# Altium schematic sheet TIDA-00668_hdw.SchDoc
size 431 x 279 mm; Date: Not shown in title block; ApprovedBy: Not shown in title block; CheckedBy: Not shown in title block; Author: Not shown in title block; CompanyName: Not shown in title block; Engineer: Not shown in title block; Organization: Not shown in title block; Address1: Not shown in title block; Address2: Not shown in title block; Address3: Not shown in title block; Address4: Not shown in title block; DocumentNumber: 1; Revision: Use project parameter SCH_Rev; SheetNumber: 3; SheetTotal: 3; PageSetup: Record=PageOptions¦CenterHorizontal=True¦CenterVertical=True¦PrintScale=1.00¦XCorrection=1.00¦YCorrection=1.00¦PrintKind=0¦BorderSize=5000000¦LeftOffset=0¦BottomOffset=0¦Orientation=2¦PaperLength=1000¦PaperWidth=1000¦Scale=100¦PaperSource=15¦PrintQuality=600¦MediaType=1¦DitherType=10¦PaperKind=Letter¦PrintScaleMode=1
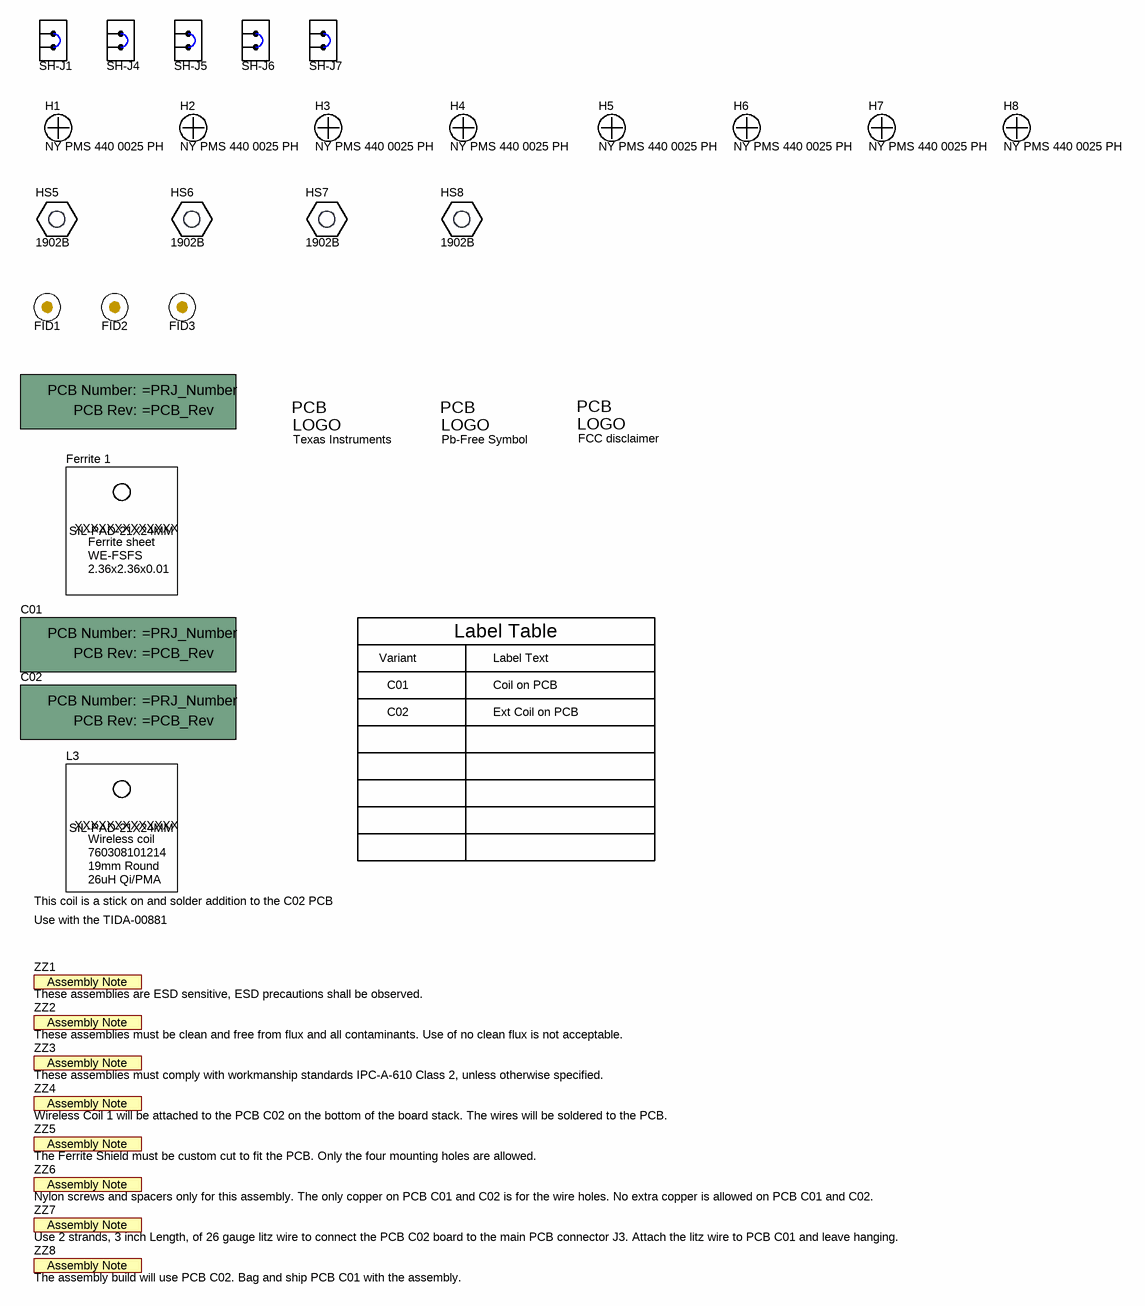
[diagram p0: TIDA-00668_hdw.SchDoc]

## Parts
(Parts that share a designator on the sheet are numbered #1, #2 ... from top to bottom, then left to right.)
!PCB1  Printed Circuit Board  (value not drawn)  (mechanical)
!PCB?#1  value C01  (hidden comment: Printed Circuit Board)  (mechanical)
!PCB?#2  value C02  (hidden comment: Printed Circuit Board)  (mechanical)
Ferrite_1  CompType: Ferrite sheet  PackageReference: 2.36x2.36x0.01  Mask: XXXXXXXXXXXXX  [SIL-PAD_24X21MM]  (hidden comment: WE-FSFS)
FID1  Fiducial  [Fiducial10-20]  (value not drawn)
FID2  Fiducial  [Fiducial10-20]  (value not drawn)
FID3  Fiducial  [Fiducial10-20]  (value not drawn)
H1  NY PMS 440 0025 PH  [NY PMS 440 0025 PH]
H2  NY PMS 440 0025 PH  [NY PMS 440 0025 PH]
H3  NY PMS 440 0025 PH  [NY PMS 440 0025 PH]
H4  NY PMS 440 0025 PH  [NY PMS 440 0025 PH]
H5  NY PMS 440 0025 PH  [NY PMS 440 0025 PH]
H6  NY PMS 440 0025 PH  [NY PMS 440 0025 PH]
H7  NY PMS 440 0025 PH  [NY PMS 440 0025 PH]
H8  NY PMS 440 0025 PH  [NY PMS 440 0025 PH]
HS5  1902B  [Keystone_1902B]
HS6  1902B  [Keystone_1902B]
HS7  1902B  [Keystone_1902B]
HS8  1902B  [Keystone_1902B]
L3  value 26uH Qi/PMA  PackageReference: 19mm Round  Note: Use with the TIDA-00881  Mask: XXXXXXXXXXXXX  [SIL-PAD_24X21MM]  (hidden comment: 760308101214)
Logo1  Texas Instruments  [TI_Symbol_Overlay_Small]  (no BOM)
Logo2  Pb-Free Symbol  [Pb-Free_Overlay_Small]  (no BOM)
Logo3  FCC disclaimer  [FCC_disclaimer]  (no BOM)
SH-J1  969102-0000-DA  [SNT-100-BK-G]  (value not drawn)
SH-J4  969102-0000-DA  [SNT-100-BK-G]  (value not drawn)
SH-J5  969102-0000-DA  [SNT-100-BK-G]  (value not drawn)
SH-J6  969102-0000-DA  [SNT-100-BK-G]  (value not drawn)
SH-J7  969102-0000-DA  [SNT-100-BK-G]  (value not drawn)
ZZ1  These assemblies are ESD sensitive, ESD precautions shall be observed.  [AssemblyNote]  (no BOM)
ZZ2  These assemblies must be clean and free from flux and all contaminants. Use of no clean flux is not acceptable.  [AssemblyNote]  (no BOM)
ZZ3  These assemblies must comply with workmanship standards IPC-A-610 Class 2, unless otherwise specified.  [AssemblyNote]  (no BOM)
ZZ4  Wireless Coil 1 will be attached to the PCB C02 on the bottom of the board stack. The wires will be soldered to the PCB.  [AssemblyNote]  (no BOM)
ZZ5  The Ferrite Shield must be custom cut to fit the PCB. Only the four mounting holes are allowed.  [AssemblyNote]  (no BOM)
ZZ6  Nylon screws and spacers only for this assembly. The only copper on PCB C01 and C02 is for the wire holes. No extra copper is allowed on PCB C01 and C02.  [AssemblyNote]  (no BOM)
ZZ7  Use 2 strands, 3 inch Length, of 26 gauge litz wire to connect the PCB C02 board to the main PCB connector J3. Attach the litz wire to PCB C01 and leave hanging.  [AssemblyNote]  (no BOM)
ZZ8  The assembly build will use PCB C02. Bag and ship PCB C01 with the assembly.  [AssemblyNote]  (no BOM)

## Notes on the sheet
- Variant
- Label Text
- Label Table
- C01
- C02
- Coil on PCB
- Ext Coil on PCB
- This coil is a stick on and solder addition to the C02 PCB

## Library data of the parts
!PCB1 = PCB: Manufacturer: Any; SymbolCreator: a0412235
!PCB?#1 = PCB: Manufacturer: Any; PartNumber: PR2228E1_C01; SymbolCreator: a0412235
!PCB?#2 = PCB: Manufacturer: Any; PartNumber: PR2228E1_C02; SymbolCreator: a0412235
Ferrite_1 = SP900S-0.009-00-114: Ferrite shield; Manufacturer: Wurth; SymbolCreator: a0799628
FID1-FID3 = Fiducial: Fiducial mark.  There is nothing to buy or mount.; SymbolCreator: codlsc
H1-H8 = NY PMS 440 0025 PH: Machine Screw, Round, #4-40 x 1/4, Nylon, Philips panhead; Manufacturer: B&F Fastener Supply; CompType: Hardware; SymbolCreator: codlsc; U/M: EA
HS5-HS8 = 1902B: Standoff, Hex, 0.375"L #4-40 Nylon; Manufacturer: Keystone; SymbolCreator: a0412235; CompType: Hardware
L3 = SP900S-0.009-00-114: Wireless coil; Manufacturer: Wurth; SymbolCreator: a0799628
Logo1 = TI_Logo: Texas Instrument Corporate Signature; SymbolCreator: codlsc
Logo2 = Pb-Free: SymbolCreator: a0412235
Logo3 = FCC_disclaimer: SymbolCreator: codlsc
SH-J1 SH-J4-SH-J7 = 969102-0000-DA: Shunt, 100mil, Gold plated, Black; Manufacturer: 3M; Alternate Manufacturer: Samtec; Value: 1x2; Note: You can "mate" this to a header by matching the designator.  i.e. use SH-J3 for header J3
ZZ1-ZZ8 = AssemblyNote: SymbolCreator: codlsc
